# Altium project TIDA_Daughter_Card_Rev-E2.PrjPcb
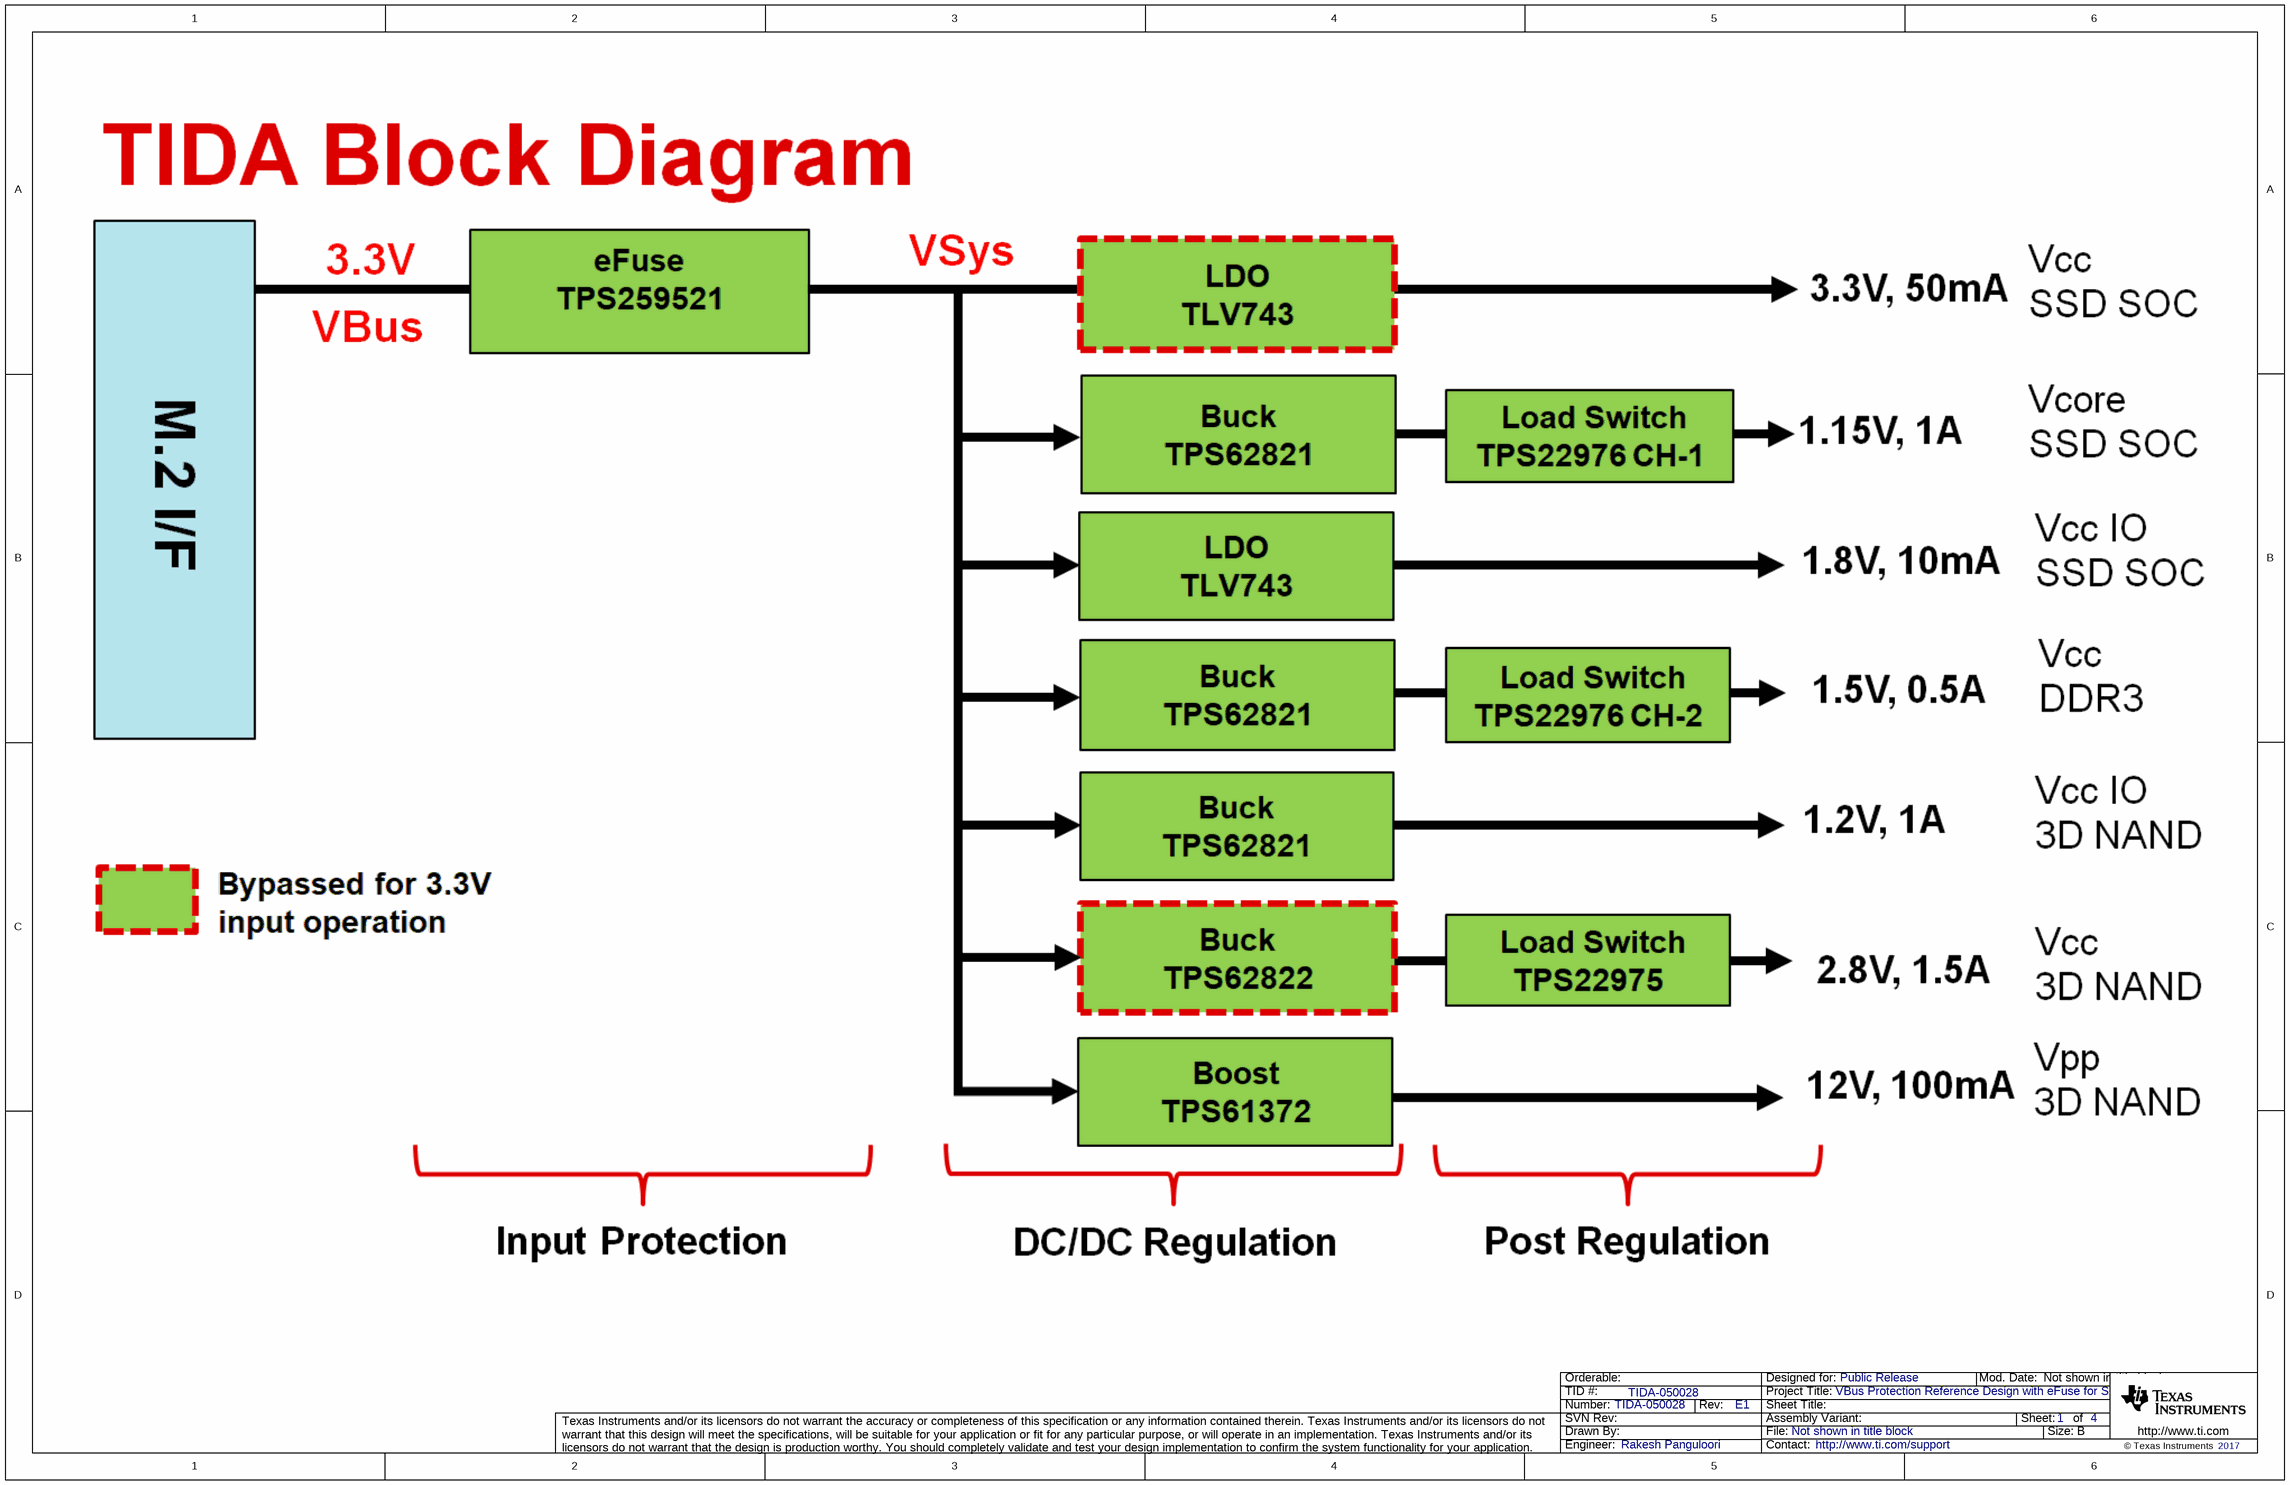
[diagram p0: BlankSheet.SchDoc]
CopyrightYear: 2017; PCB_Layout: Tessolve; PCB_Rev: E2; PRJ_Customer: Public Release; PRJ_Engineer: Rakesh Panguloori; PRJ_Number: TIDA-050028; PRJ_Title: VBus Protection Reference Design with eFuse for SSD Modules; SCH_Rev: E1; TechSupport: http://www.ti.com/support; TID: TIDA-050028
4 sheets, 81 parts. Net scope: flat (ports and power ports of the same name join across sheets).
Board file: TIDA_Daughter_Card_Rev-E2.PcbDoc
Sheets:
  BlankSheet.SchDoc
  Daughter_Card_Sheet1.SchDoc
  Daughter_Card_Sheet2.SchDoc
  EVM_Hardware.SchDoc

## Sheet BlankSheet.SchDoc
size 431 x 279 mm; Date: Not shown in title block; ApprovedBy: Not shown in title block; CheckedBy: Not shown in title block; Author: Not shown in title block; CompanyName: Not shown in title block; Engineer: Not shown in title block; Organization: Not shown in title block; Address1: Not shown in title block; Address2: Not shown in title block; Address3: Not shown in title block; Address4: Not shown in title block; DocumentNumber: 1; Revision: Use project parameter SCH_Rev; SheetNumber: 1; SheetTotal: 4; PageSetup: Record=PageOptions¦CenterHorizontal=True¦CenterVertical=True¦PrintScale=1.00¦XCorrection=1.00¦YCorrection=1.00¦PrintKind=0¦BorderSize=5000000¦LeftOffset=0¦BottomOffset=0¦Orientation=2¦PaperLength=1000¦PaperWidth=1000¦Scale=100¦PaperSource=15¦PrintQuality=600¦MediaType=1¦DitherType=10¦PaperKind=Letter¦PrintScaleMode=1; Orderable: N/A

## Sheet Daughter_Card_Sheet1.SchDoc
size 431 x 279 mm; Date: Not shown in title block; ApprovedBy: Not shown in title block; CheckedBy: Not shown in title block; Author: Not shown in title block; CompanyName: Not shown in title block; Engineer: Not shown in title block; Organization: Not shown in title block; Address1: Not shown in title block; Address2: Not shown in title block; Address3: Not shown in title block; Address4: Not shown in title block; DocumentNumber: 1; Revision: Use project parameter SCH_Rev; SheetNumber: 2; SheetTotal: 4; PageSetup: Record=PageOptions¦CenterHorizontal=True¦CenterVertical=True¦PrintScale=1.00¦XCorrection=1.00¦YCorrection=1.00¦PrintKind=0¦BorderSize=5000000¦LeftOffset=0¦BottomOffset=0¦Orientation=2¦PaperLength=1000¦PaperWidth=1000¦Scale=100¦PaperSource=15¦PrintQuality=600¦MediaType=1¦DitherType=10¦PaperKind=Letter¦PrintScaleMode=1; Orderable: N/A
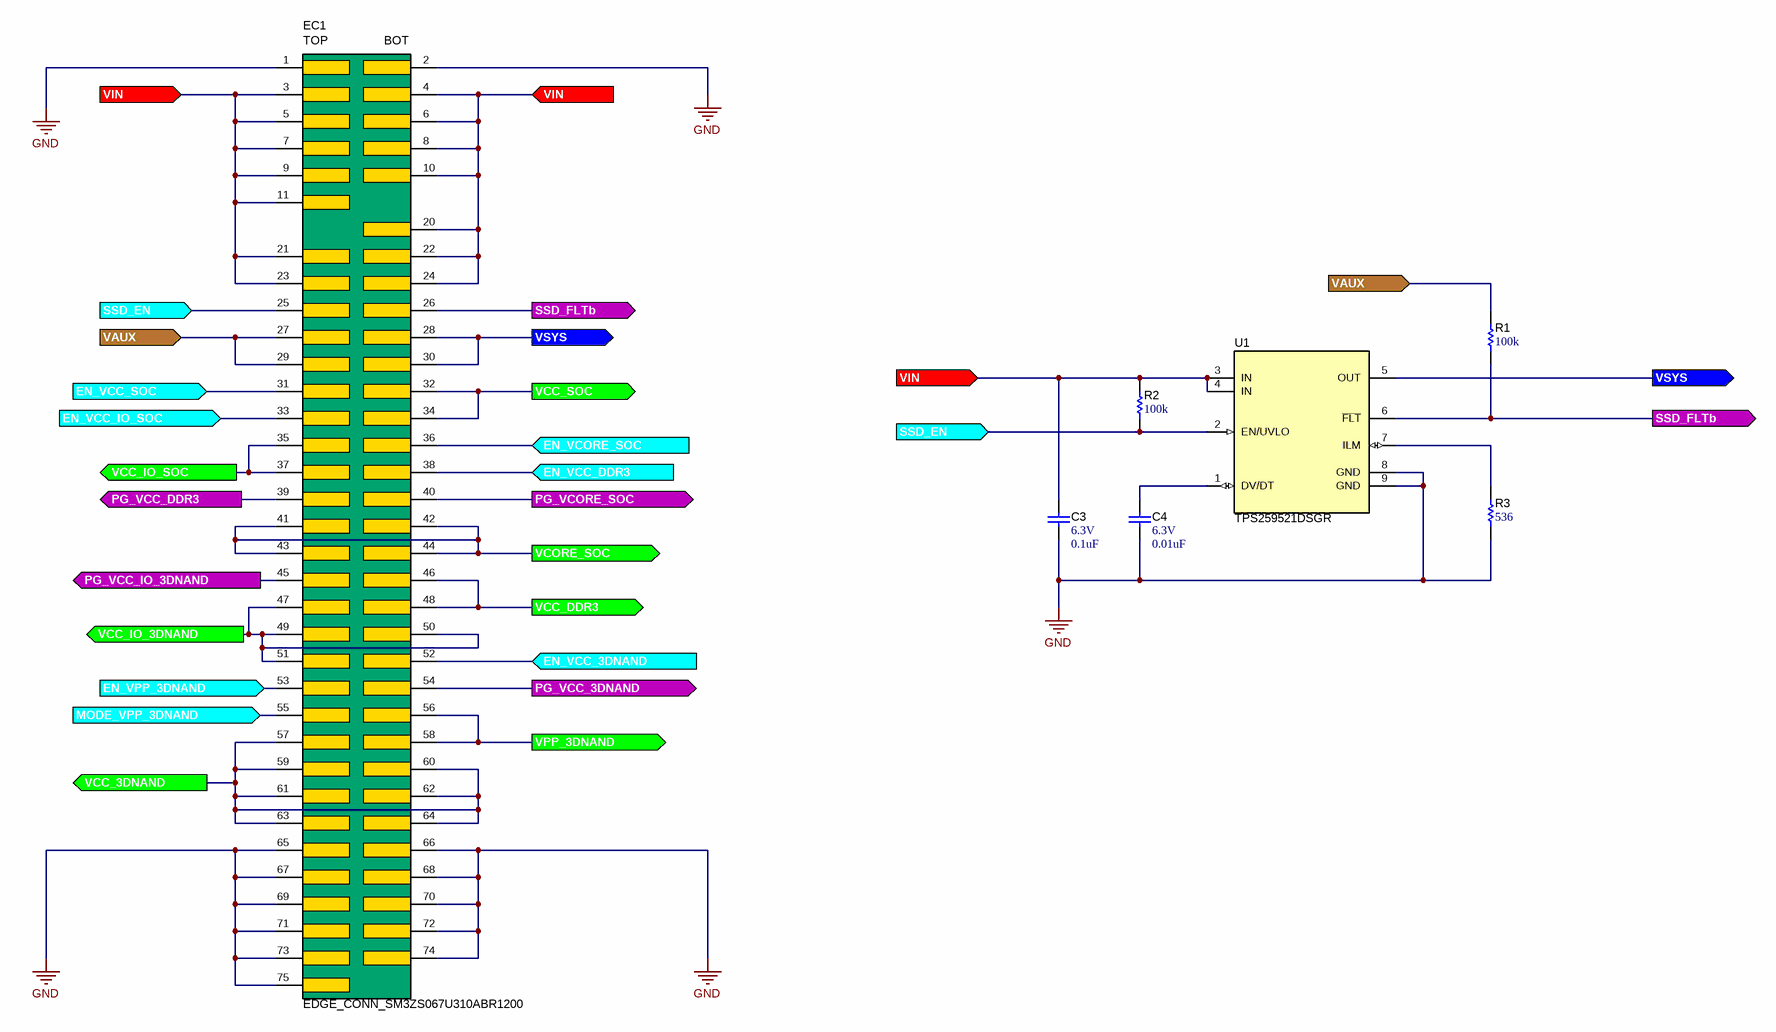
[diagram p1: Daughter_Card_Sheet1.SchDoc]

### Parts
C3  VDC_V: 6.3V  ValueDisplayed: 0.1uF  [0201_033]  (hidden comment: GRM033R60J104KE19D)
C4  VDC_V: 6.3V  ValueDisplayed: 0.01uF  [0201]  (hidden comment: GRM033R60J103KA01D)
EC1  EDGE_CONN_SM3ZS067U310ABR1200  [JAE_EDGE_CONN_SM3ZS067U310ABR1200]  (no BOM)
R1  ValueDisplayed: 100k  [0201]  (hidden comment: RC0201JR-07100KL)
R2  ValueDisplayed: 100k  [0201]  (hidden comment: RC0201JR-07100KL)
R3  ValueDisplayed: 536  [0201]  (hidden comment: RC0201FR-07536RL)
U1  TPS259521DSGR  [DSG0008A]

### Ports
EN_VCC_3DNAND (in), EN_VCC_DDR3 (in), EN_VCC_IO_SOC (in), EN_VCC_SOC (in), EN_VCORE_SOC (in), EN_VPP_3DNAND (in), MODE_VPP_3DNAND (in), PG_VCC_3DNAND (out), PG_VCC_DDR3 (out), PG_VCC_IO_3DNAND (out), PG_VCORE_SOC (out), SSD_EN (in), SSD_FLTb (out), VAUX (in), VCC_3DNAND (out), VCC_DDR3 (out), VCC_IO_3DNAND (out), VCC_IO_SOC (out), VCC_SOC (out), VCORE_SOC (out), VIN (in), VPP_3DNAND (out), VSYS (out)

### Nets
GND: C3.2 C4.2 EC1.1 EC1.2 EC1.65 EC1.66 EC1.67 EC1.68 EC1.69 EC1.70 EC1.71 EC1.72 EC1.73 EC1.74 EC1.75 R3.1 U1.8(GND) U1.9(GND)
EN_VCC_3DNAND: EC1.52 ; port EN_VCC_3DNAND
EN_VCC_DDR3: EC1.38 ; port EN_VCC_DDR3
EN_VCC_IO_SOC: EC1.33 ; port EN_VCC_IO_SOC
EN_VCC_SOC: EC1.31 ; port EN_VCC_SOC
EN_VCORE_SOC: EC1.36 ; port EN_VCORE_SOC
EN_VPP_3DNAND: EC1.53 ; port EN_VPP_3DNAND
MODE_VPP_3DNAND: EC1.55 ; port MODE_VPP_3DNAND
PG_VCC_3DNAND: EC1.54 ; port PG_VCC_3DNAND
PG_VCC_DDR3: EC1.39 ; port PG_VCC_DDR3
PG_VCC_IO_3DNAND: EC1.45 ; port PG_VCC_IO_3DNAND
PG_VCORE_SOC: EC1.40 ; port PG_VCORE_SOC
SSD_EN: EC1.25 R2.1 U1.2(EN/UVLO) ; port SSD_EN
SSD_FLTb: EC1.26 R1.1 U1.6(~{FLT}) ; port SSD_FLTb
VAUX: EC1.27 EC1.29 R1.2 ; port VAUX
VCC_3DNAND: EC1.57 EC1.59 EC1.60 EC1.61 EC1.62 EC1.63 EC1.64 ; port VCC_3DNAND
VCC_DDR3: EC1.46 EC1.48 ; port VCC_DDR3
VCC_IO_3DNAND: EC1.47 EC1.49 EC1.50 EC1.51 ; port VCC_IO_3DNAND
VCC_IO_SOC: EC1.35 EC1.37 ; port VCC_IO_SOC
VCC_SOC: EC1.32 EC1.34 ; port VCC_SOC
VCORE_SOC: EC1.41 EC1.42 EC1.43 EC1.44 ; port VCORE_SOC
VIN: C3.1 EC1.3 EC1.4 EC1.5 EC1.6 EC1.7 EC1.8 EC1.9 EC1.10 EC1.11 EC1.20 EC1.21 EC1.22 EC1.23 EC1.24 R2.2 U1.3(IN) U1.4(IN) ; port VIN
VPP_3DNAND: EC1.56 EC1.58 ; port VPP_3DNAND
VSYS: EC1.28 EC1.30 U1.5(OUT) ; port VSYS
NetC4_1: C4.1 U1.1(DV/DT)
NetR3_2: R3.2 U1.7(ILM)

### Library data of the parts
C3 = CMP-0009690-3: CAP, CERM, 0.1 uF, 6.3 V, +/- 10%, X5R, 0201; Manufacturer: MuRata; TaMin_C: -55°C; Polarized: N; SizeAreaWB_mm2: 2.08; Value1: Unknown; U/M: EA; Value: 0.1uF; TaMax_C: 85°C; SizeZ_mm: 0.33; SizeX_mm: 0.6; SizeY_mm: 0.3; Cap_Case: 0201; SizeArea_mm2: 0.18; Cap_F: 100nF; AEC Category: Q200
C4 = CMP-0009689-3: CAP, CERM, 0.01 uF, 6.3 V, +/- 10%, X5R, 0201; Manufacturer: MuRata; TaMin_C: -55°C; Polarized: N; SizeAreaWB_mm2: 2.08; Value1: Unknown; U/M: EA; Value: 0.01uF; TaMax_C: 85°C; SizeZ_mm: 0.26; SizeX_mm: 0.6; SizeY_mm: 0.3; SizeArea_mm2: 0.18; Cap_F: 10nF; AEC Category: Q200
EC1 = CMP-0075074-1: Connector, Card Edge 67-Pos, 0.5-mm Pitch, B Key; Manufacturer: JAE Electronics; CT: True; CompType: Card Edge Footprint; CNHeader: False
R1 R2 = CMP-0027017-1: RES, 100 k, 5%, 0.05 W, 0201; Manufacturer: Yageo America; Power_W: 50mW; TempCo: 200 ppm/C; U/M: EA; Value: 100k; EIA_Code: E24; SizeX_mm: 0.6; SizeY_mm: 0.3; SizeZ_mm: 0.26; Value2: 0.05W; SizeArea_mm2: 0.18; AEC Qualified: N; VDC_V: 25V; AEC Category: Q200
R3 = CMP-0027765-1: RES, 536, 1%, 0.05 W, 0201; Manufacturer: Yageo America; Power_W: 50mW; TempCo: 200 ppm/C; Value_Code: 536R; U/M: EA; Value: 536; EIA_Code: E96; SizeX_mm: 0.6; SizeY_mm: 0.3; SizeZ_mm: 0.26; Value2: 0.05W; SizeArea_mm2: 0.18; AEC Qualified: N; VDC_V: 25V; AEC Category: Q200
U1 = CMP-0013452-3: 12V eFuse with Over Voltage Protection, DSG0008A (WSON-8); Alternate PartNumber: TPS259521DSGT; Manufacturer: Texas Instruments; SizeZ_mm: 0.8; SizeX_mm: 2; SizeArea_mm2: 4; CompType: IC; U/M: EA; SizeAreaWB_mm2: 9

## Sheet Daughter_Card_Sheet2.SchDoc
size 431 x 279 mm; Date: Not shown in title block; ApprovedBy: Not shown in title block; CheckedBy: Not shown in title block; Author: Not shown in title block; CompanyName: Not shown in title block; Engineer: Not shown in title block; Organization: Not shown in title block; Address1: Not shown in title block; Address2: Not shown in title block; Address3: Not shown in title block; Address4: Not shown in title block; DocumentNumber: 1; Revision: Use project parameter SCH_Rev; SheetNumber: 3; SheetTotal: 4; PageSetup: Record=PageOptions¦CenterHorizontal=True¦CenterVertical=True¦PrintScale=1.00¦XCorrection=1.00¦YCorrection=1.00¦PrintKind=0¦BorderSize=5000000¦LeftOffset=0¦BottomOffset=0¦Orientation=2¦PaperLength=1000¦PaperWidth=1000¦Scale=100¦PaperSource=15¦PrintQuality=600¦MediaType=1¦DitherType=10¦PaperKind=Letter¦PrintScaleMode=1; Orderable: N/A
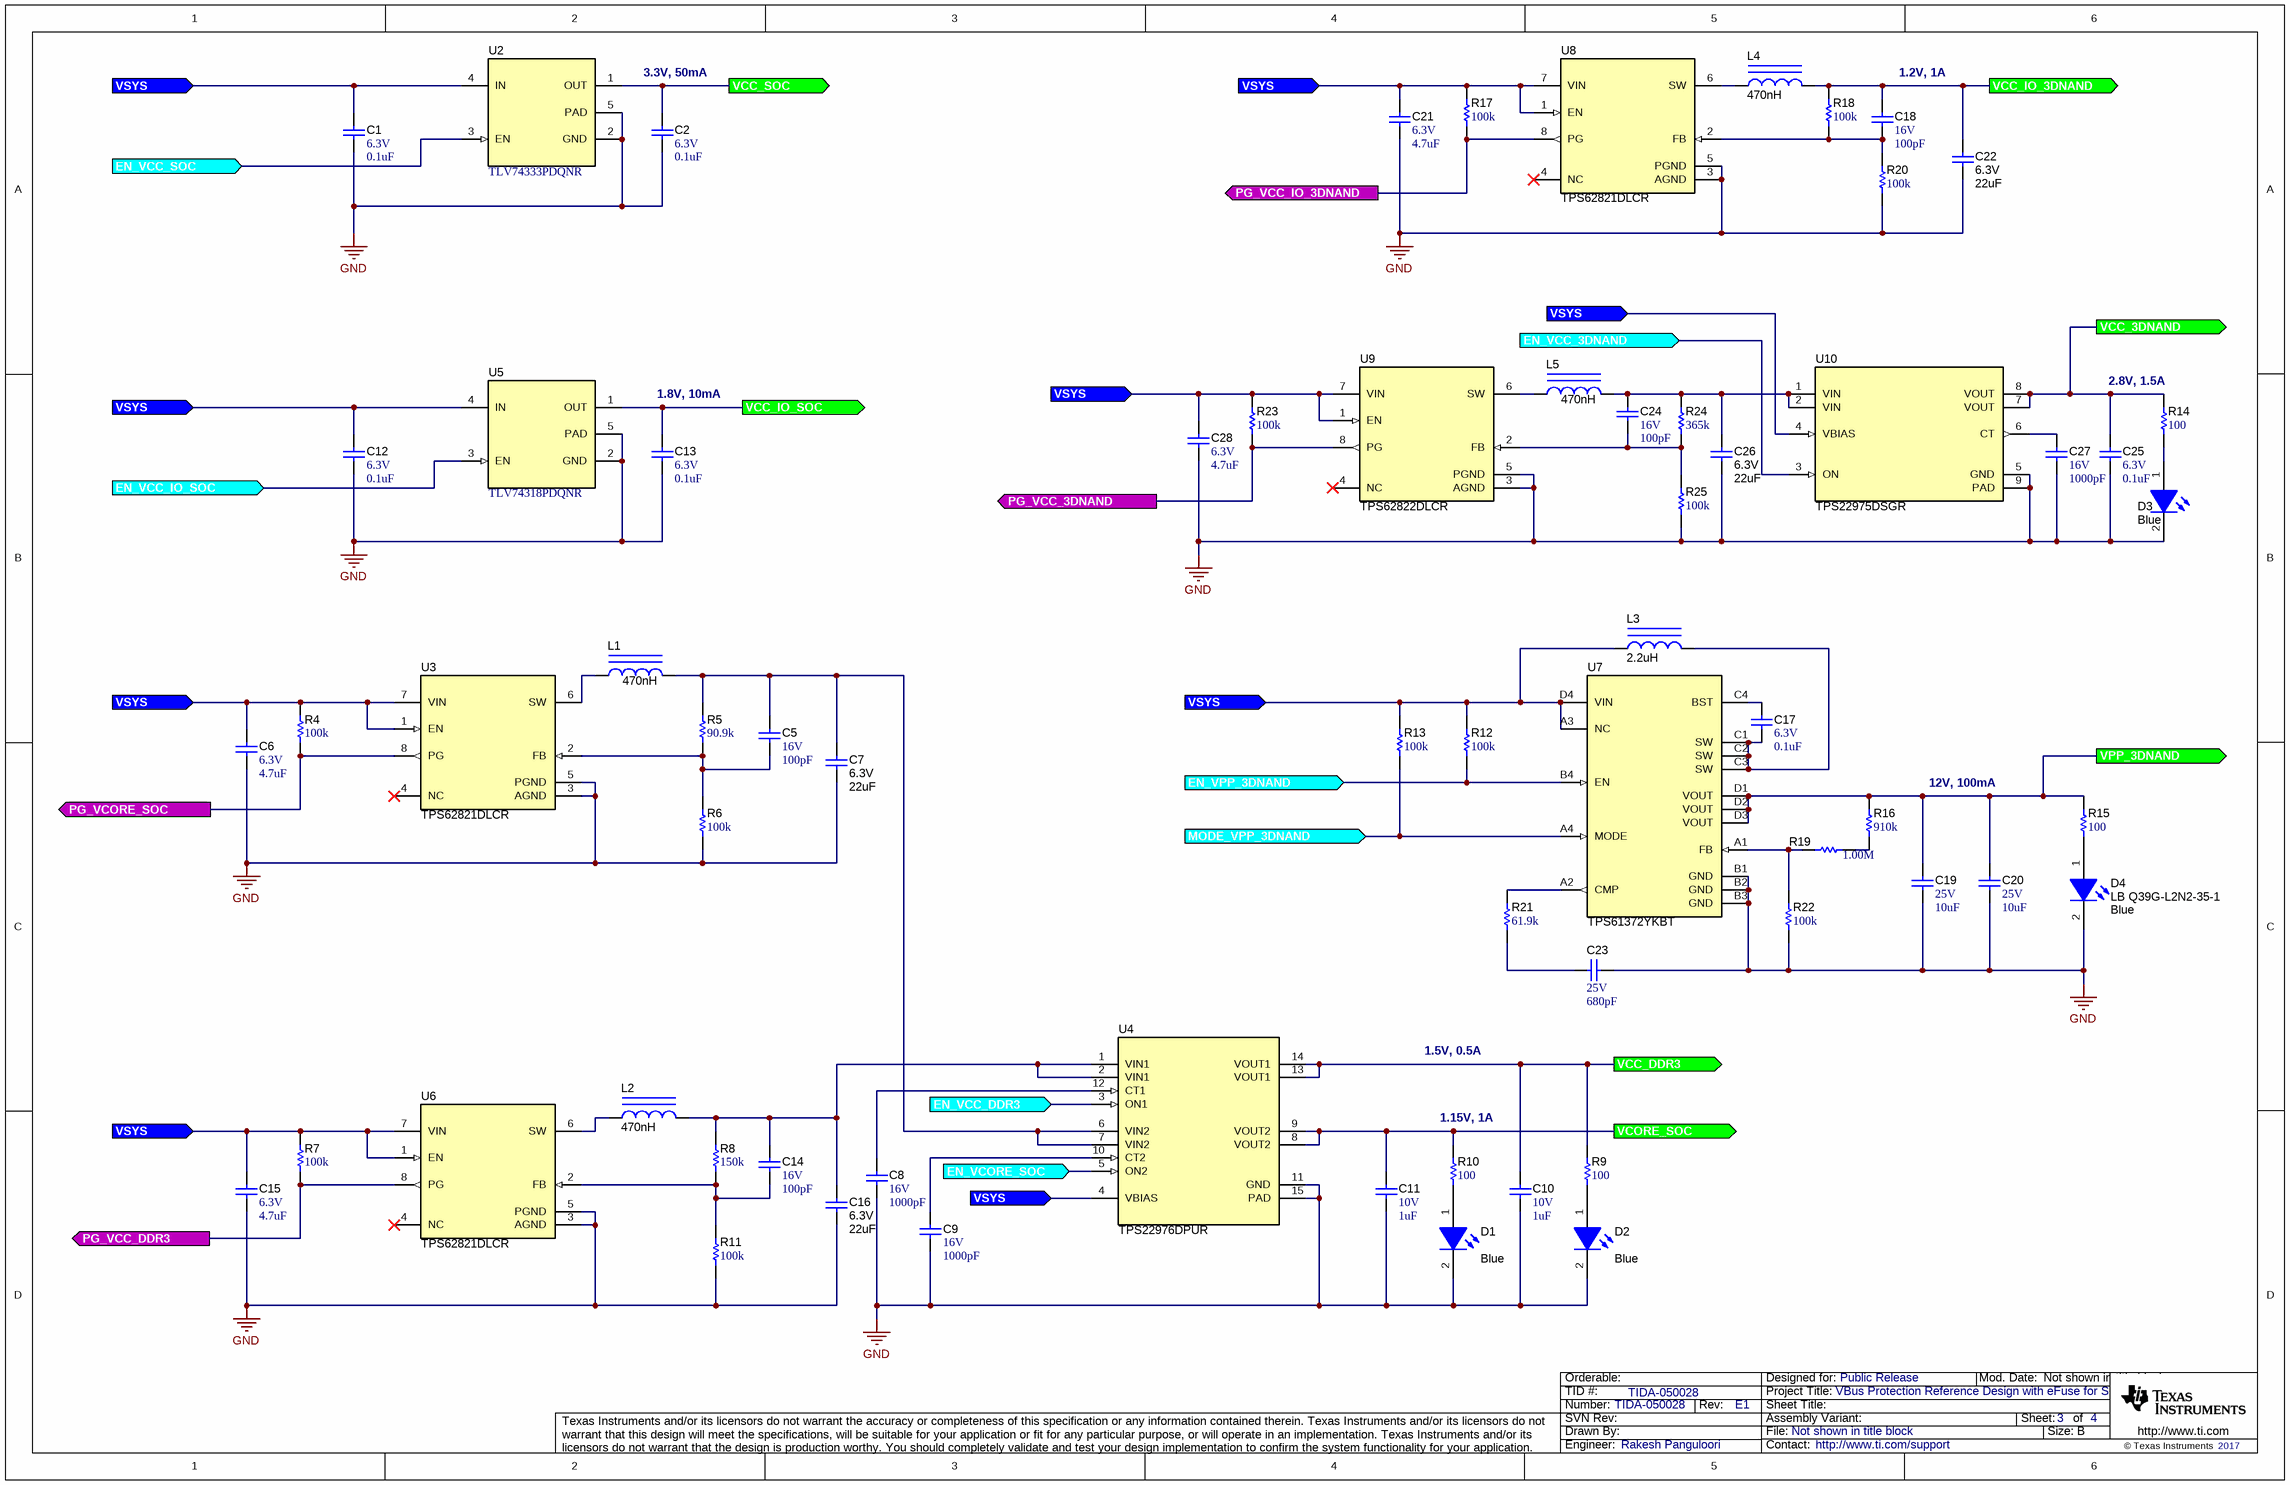
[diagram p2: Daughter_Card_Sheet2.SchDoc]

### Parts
C1  VDC_V: 6.3V  ValueDisplayed: 0.1uF  [0201_033]  (hidden comment: GRM033R60J104KE19D)
C2  VDC_V: 6.3V  ValueDisplayed: 0.1uF  [0201_033]  (hidden comment: GRM033R60J104KE19D)
C5  VDC_V: 16V  ValueDisplayed: 100pF  [0201]  (hidden comment: GRM033R71C101KA01D)
C6  VDC_V: 6.3V  ValueDisplayed: 4.7uF  [0201]  (hidden comment: GRM035R60J475ME15D)
C7  VDC_V: 6.3V  ValueDisplayed: 22uF  [0402S]  (hidden comment: GRM155R60J226ME11D)
C8  VDC_V: 16V  ValueDisplayed: 1000pF  [0201]  (hidden comment: GRM033R71C102KA01D)
C9  VDC_V: 16V  ValueDisplayed: 1000pF  [0201]  (hidden comment: GRM033R71C102KA01D)
C10  VDC_V: 10V  ValueDisplayed: 1uF  [0201]  (hidden comment: CL03A105MP3NSNC)
C11  VDC_V: 10V  ValueDisplayed: 1uF  [0201]  (hidden comment: CL03A105MP3NSNC)
C12  VDC_V: 6.3V  ValueDisplayed: 0.1uF  [0201_033]  (hidden comment: GRM033R60J104KE19D)
C13  VDC_V: 6.3V  ValueDisplayed: 0.1uF  [0201_033]  (hidden comment: GRM033R60J104KE19D)
C14  VDC_V: 16V  ValueDisplayed: 100pF  [0201]  (hidden comment: GRM033R71C101KA01D)
C15  VDC_V: 6.3V  ValueDisplayed: 4.7uF  [0201]  (hidden comment: GRM035R60J475ME15D)
C16  VDC_V: 6.3V  ValueDisplayed: 22uF  [0402S]  (hidden comment: GRM155R60J226ME11D)
C17  VDC_V: 6.3V  ValueDisplayed: 0.1uF  [0201_033]  (hidden comment: GRM033R60J104KE19D)
C18  VDC_V: 16V  ValueDisplayed: 100pF  [0201]  (hidden comment: GRM033R71C101KA01D)
C19  VDC_V: 25V  ValueDisplayed: 10uF  [0603]  (hidden comment: GRM188R61E106MA73D)
C20  VDC_V: 25V  ValueDisplayed: 10uF  [0603]  (hidden comment: GRM188R61E106MA73D)
C21  VDC_V: 6.3V  ValueDisplayed: 4.7uF  [0201]  (hidden comment: GRM035R60J475ME15D)
C22  VDC_V: 6.3V  ValueDisplayed: 22uF  [0402L]  (hidden comment: GRM155R60J226ME11D)
C23  VDC_V: 25V  ValueDisplayed: 680pF  [0201]  (hidden comment: GRM033R71E681KA01D)
C24  VDC_V: 16V  ValueDisplayed: 100pF  [0201]  (hidden comment: GRM033R71C101KA01D)
C25  VDC_V: 6.3V  ValueDisplayed: 0.1uF  [0201_033]  (hidden comment: GRM033R60J104KE19D)
C26  VDC_V: 6.3V  ValueDisplayed: 22uF  [0402L]  (hidden comment: GRM155R60J226ME11D)
C27  VDC_V: 16V  ValueDisplayed: 1000pF  [0201]  (hidden comment: GRM033R71C102KA01D)
C28  VDC_V: 6.3V  ValueDisplayed: 4.7uF  [0201]  (hidden comment: GRM035R60J475ME15D)
D1  value Blue  [LB Q39G_BLUE]  (hidden comment: LB Q39G-L2N2-35-1)
D2  value Blue  [LB Q39G_BLUE]  (hidden comment: LB Q39G-L2N2-35-1)
D3  value Blue  [LB Q39G_BLUE]  (hidden comment: LB Q39G-L2N2-35-1)
D4  LB Q39G-L2N2-35-1  value Blue  [LB Q39G_BLUE]
L1  ValueDisplayed: 470nH  [DFE201610E]  (hidden comment: DFE201610E-R47M=P2)
L2  ValueDisplayed: 470nH  [DFE201610E]  (hidden comment: DFE201610E-R47M=P2)
L3  ValueDisplayed: 2.2uH  [DFE322512]  (hidden comment: DFE322512F-2R2M=P2)
L4  ValueDisplayed: 470nH  [DFE201610E]  (hidden comment: DFE201610E-R47M=P2)
L5  ValueDisplayed: 470nH  [DFE201610E]  (hidden comment: DFE201610E-R47M=P2)
R4  ValueDisplayed: 100k  [0201]  (hidden comment: RC0201JR-07100KL)
R5  ValueDisplayed: 90.9k  [0201]  (hidden comment: RC0201FR-0790K9L)
R6  ValueDisplayed: 100k  [0201]  (hidden comment: RC0201JR-07100KL)
R7  ValueDisplayed: 100k  [0201]  (hidden comment: RC0201JR-07100KL)
R8  ValueDisplayed: 150k  [0201]  (hidden comment: RC0201FR-07150KL)
R9  ValueDisplayed: 100  [0201]  (hidden comment: RC0201JR-07100RL)
R10  ValueDisplayed: 100  [0201]  (hidden comment: RC0201JR-07100RL)
R11  ValueDisplayed: 100k  [0201]  (hidden comment: RC0201JR-07100KL)
R12  ValueDisplayed: 100k  [0201]  (hidden comment: RC0201JR-07100KL)
R13  ValueDisplayed: 100k  [0201]  (hidden comment: RC0201JR-07100KL)
R14  ValueDisplayed: 100  [0201]  (hidden comment: RC0201JR-07100RL)
R15  ValueDisplayed: 100  [0201]  (hidden comment: RC0201JR-07100RL)
R16  ValueDisplayed: 910k  [0201]  (hidden comment: RC0201JR-07910KL)
R17  ValueDisplayed: 100k  [0201]  (hidden comment: RC0201JR-07100KL)
R18  ValueDisplayed: 100k  [0201]  (hidden comment: RC0201JR-07100KL)
R19  ValueDisplayed: 1.00M  [0201]  (hidden comment: RC0201FR-071ML)
R20  ValueDisplayed: 100k  [0201]  (hidden comment: RC0201JR-07100KL)
R21  ValueDisplayed: 61.9k  [0201]  (hidden comment: RC0201FR-0761K9L)
R22  ValueDisplayed: 100k  [0201]  (hidden comment: RC0201JR-07100KL)
R23  ValueDisplayed: 100k  [0201]  (hidden comment: RC0201JR-07100KL)
R24  ValueDisplayed: 365k  [0201]  (hidden comment: RC0201FR-07365KL)
R25  ValueDisplayed: 100k  [0201]  (hidden comment: RC0201JR-07100KL)
U2  TLV74333PDQNR  [DQN0004A]
U3  TPS62821DLCR  [DLC0008A]
U4  TPS22976DPUR  [DPU0014A]
U5  TLV74318PDQNR  [DQN0004A]
U6  TPS62821DLCR  [DLC0008A]
U7  TPS61372YKBT  [YKB0016AEAG]
U8  TPS62821DLCR  [DLC0008A]
U9  TPS62822DLCR  [DLC0008A]
U10  TPS22975DSGR  [DSG0008A]

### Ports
EN_VCC_3DNAND (in), EN_VCC_DDR3 (in), EN_VCC_IO_SOC (in), EN_VCC_SOC (in), EN_VCORE_SOC (in), EN_VPP_3DNAND (in), MODE_VPP_3DNAND (in), PG_VCC_3DNAND (out), PG_VCC_DDR3 (out), PG_VCC_IO_3DNAND (out), PG_VCORE_SOC (out), VCC_3DNAND (out), VCC_DDR3 (out), VCC_IO_3DNAND (out), VCC_IO_SOC (out), VCC_SOC (out), VCORE_SOC (out), VPP_3DNAND (out), VSYS (in)

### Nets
GND: C1.2 C2.2 C6.2 C7.2 C8.2 C9.2 C10.2 C11.2 C12.2 C13.2 C15.2 C16.2 C19.2 C20.2 C21.2 C22.2 C23.1 C25.2 C26.2 C27.2 C28.2 D1.2(K) D2.2(K) D3.2(K) D4.2(K) R6.1 R11.1 R20.1 R22.1 R25.1 U2.2(GND) U2.5(PAD) U3.3(AGND) U3.5(PGND) U4.11(GND) U4.15(PAD) U5.2(GND) U5.5(PAD) U6.3(AGND) U6.5(PGND) U7.B1(GND) U7.B2(GND) U7.B3(GND) U8.3(AGND) U8.5(PGND) U9.3(AGND) U9.5(PGND) U10.5(GND) U10.9(PAD)
EN_VCC_3DNAND: U10.3(ON) ; port EN_VCC_3DNAND
EN_VCC_DDR3: U4.3(ON1) ; port EN_VCC_DDR3
EN_VCC_IO_SOC: U5.3(EN) ; port EN_VCC_IO_SOC
EN_VCC_SOC: U2.3(EN) ; port EN_VCC_SOC
EN_VCORE_SOC: U4.5(ON2) ; port EN_VCORE_SOC
EN_VPP_3DNAND: R12.1 U7.B4(EN) ; port EN_VPP_3DNAND
MODE_VPP_3DNAND: R13.2 U7.A4(MODE) ; port MODE_VPP_3DNAND
PG_VCC_3DNAND: R23.1 U9.8(PG) ; port PG_VCC_3DNAND
PG_VCC_DDR3: R7.1 U6.8(PG) ; port PG_VCC_DDR3
PG_VCC_IO_3DNAND: R17.1 U8.8(PG) ; port PG_VCC_IO_3DNAND
PG_VCORE_SOC: R4.1 U3.8(PG) ; port PG_VCORE_SOC
VCC_3DNAND: C25.1 R14.2 U10.7(VOUT) U10.8(VOUT) ; port VCC_3DNAND
VCC_DDR3: C10.1 R9.2 U4.13(VOUT1) U4.14(VOUT1) ; port VCC_DDR3
VCC_IO_3DNAND: C18.1 C22.1 L4.2 R18.2 ; port VCC_IO_3DNAND
VCC_IO_SOC: C13.1 U5.1(OUT) ; port VCC_IO_SOC
VCC_SOC: C2.1 U2.1(OUT) ; port VCC_SOC
VCORE_SOC: C11.1 R10.2 U4.8(VOUT2) U4.9(VOUT2) ; port VCORE_SOC
VPP_3DNAND: C19.1 C20.1 R15.2 R16.2 U7.D1(VOUT) U7.D2(VOUT) U7.D3(VOUT) ; port VPP_3DNAND
VSYS: C1.1 C6.1 C12.1 C15.1 C21.1 C28.1 L3.1 R4.2 R7.2 R12.2 R13.1 R17.2 R23.2 U2.4(IN) U3.1(EN) U3.7(VIN) U4.4(VBIAS) U5.4(IN) U6.1(EN) U6.7(VIN) U7.A3(NC) U7.D4(VIN) U8.1(EN) U8.7(VIN) U9.1(EN) U9.7(VIN) U10.4(VBIAS) ; port VSYS
NetC5_1: C5.1 C7.1 L1.2 R5.2 U4.6(VIN2) U4.7(VIN2)
NetC5_2: C5.2 R5.1 R6.2 U3.2(FB)
NetC8_1: C8.1 U4.12(CT1)
NetC9_1: C9.1 U4.10(CT2)
NetC14_1: C14.1 C16.1 L2.2 R8.2 U4.1(VIN1) U4.2(VIN1)
NetC14_2: C14.2 R8.1 R11.2 U6.2(FB)
NetC17_1: C17.1 U7.C4(BST)
NetC17_2: C17.2 L3.2 U7.C1(SW) U7.C2(SW) U7.C3(SW)
NetC18_2: C18.2 R18.1 R20.2 U8.2(FB)
NetC23_2: C23.2 R21.1
NetC24_1: C24.1 C26.1 L5.2 R24.2 U10.1(VIN) U10.2(VIN)
NetC24_2: C24.2 R24.1 R25.2 U9.2(FB)
NetC27_1: C27.1 U10.6(CT)
NetD1_1: D1.1(A) R10.1
NetD2_1: D2.1(A) R9.1
NetD3_1: D3.1(A) R14.1
NetD4_1: D4.1(A) R15.1
NetL1_1: L1.1 U3.6(SW)
NetL2_1: L2.1 U6.6(SW)
NetL4_1: L4.1 U8.6(SW)
NetL5_1: L5.1 U9.6(SW)
NetR16_1: R16.1 R19.2
NetR19_1: R19.1 R22.2 U7.A1(FB)
NetR21_2: R21.2 U7.A2(CMP)

Not connected (* = marked no-connect by the designer): U3 4(NC)*; U6 4(NC)*; U8 4(NC)*; U9 4(NC)*

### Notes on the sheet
- 3.3V, 50mA
- (near C18) 1.2V, 1A
- 1.8V, 10mA
- (near R14) 2.8V, 1.5A
- 12V, 100mA
- 1.5V, 0.5A
- (near R10) 1.15V, 1A

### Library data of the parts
C1 C2 C12 C13 C17 C25 = CMP-0009690-3: as C3 on sheet Daughter_Card_Sheet1
C5 C14 C18 C24 = CMP-0009744-1: CAP, CERM, 100 pF, 16 V, +/- 10%, X7R, 0201; Manufacturer: MuRata; TaMin_C: -55°C; Polarized: N; SizeAreaWB_mm2: 2.08; Value1: Unknown; U/M: EA; Value: 100pF; TaMax_C: 125°C; SizeZ_mm: 0.26; SizeX_mm: 0.6; SizeY_mm: 0.3; SizeArea_mm2: 0.18; AEC Category: Q200
C6 C15 C21 C28 = CMP-0009780-1: CAP, CERM, 4.7 uF, 6.3 V, +/- 20%, X5R, 0201; Manufacturer: MuRata; TaMin_C: -55°C; Polarized: N; SizeAreaWB_mm2: 2.08; Value1: Unknown; U/M: EA; Value: 4.7uF; TaMax_C: 85°C; SizeZ_mm: 0.26; SizeX_mm: 0.6; SizeY_mm: 0.3; SizeArea_mm2: 0.18; Cap_F: 4.7µF; AEC Category: Q200
C7 = CMP-0006545-2: CAP, CERM, 22 uF, 6.3 V, +/- 20%, X5R, 0402; Manufacturer: MuRata; TaMin_C: -55°C; Polarized: N; SizeAreaWB_mm2: 3; Value1: Unknown; U/M: EA; Value: 22uF; TaMax_C: 85°C; SizeZ_mm: 0.6; SizeY_mm: 0.5; Cap_Case: 0402; SizeX_mm: 1; Cap_F: 22µF; AEC Category: Q200
C8 C9 C27 = CMP-0009745-1: CAP, CERM, 1000 pF, 16 V, +/- 10%, X7R, 0201; Manufacturer: MuRata; TaMin_C: -55°C; Polarized: N; SizeAreaWB_mm2: 2.08; Value1: Unknown; U/M: EA; Value: 1000pF; TaMax_C: 125°C; SizeZ_mm: 0.26; SizeX_mm: 0.6; SizeY_mm: 0.3; SizeArea_mm2: 0.18; Cap_F: 1nF; AEC Category: Q200
C10 C11 = CMP-0009656-3: CAP, CERM, 1 uF, 10 V, +/- 20%, X5R, 0201; Manufacturer: Samsung Electro-Mechanics; TaMin_C: -55°C; Polarized: N; SizeAreaWB_mm2: 2.08; Value1: Unknown; U/M: EA; Value: 1uF; TaMax_C: 85°C; SizeZ_mm: 0.26; SizeX_mm: 0.6; SizeY_mm: 0.3; SizeArea_mm2: 0.18; Cap_F: 1µF; AEC Category: Q200
C16 C22 C26 = CMP-0006545-2: CAP, CERM, 22 uF, 6.3 V, +/- 20%, X5R, 0402; Manufacturer: MuRata; TaMin_C: -55°C; Polarized: N; SizeAreaWB_mm2: 3; Value1: Unknown; U/M: EA; Value: 22uF; TaMax_C: 85°C; SizeZ_mm: 0.6; SizeY_mm: 0.5; Cap_Case: 0402; CompType: Capacitor; SizeX_mm: 1; Cap_F: 22µF; AEC Category: Q200
C19 C20 = CMP-0007344-5: CAP, CERM, 10 uF, 25 V, +/- 20%, X5R, 0603; Manufacturer: MuRata; TaMin_C: -55°C; Polarized: N; SizeAreaWB_mm2: 4.68; Value1: Unknown; U/M: EA; Value: 10uF; TaMax_C: 85°C; SizeZ_mm: 1; SizeX_mm: 1.6; SizeY_mm: 0.8; SizeArea_mm2: 1.28; Cap_F: 10µF; AEC Category: Q200
C23 = CMP-0009776-1: CAP, CERM, 680 pF, 25 V, +/- 10%, X7R, 0201; Manufacturer: MuRata; TaMin_C: -55°C; Polarized: N; SizeAreaWB_mm2: 2.08; Value1: Unknown; U/M: EA; Value: 680pF; TaMax_C: 125°C; SizeZ_mm: 0.26; SizeX_mm: 0.6; SizeY_mm: 0.3; SizeArea_mm2: 0.18; AEC Category: Q200
D1-D4 = CMP-0002849-2: LED, Blue, SMD; Manufacturer: OSRAM; Tjmax_C: 95°C; Value1: W; Io_A: 1.5dA; Vf_V: 2.85V
L1 L2 L4 L5 = CMP-0077678-3: Inductor, Shielded, Metal Composite, 470 nH, 3.6 A, 0.032 ohm, SMD; Manufacturer: MuRata; Isat: 4.8A @ 30% inductance drop; Irms: 3.6A @ 40C rise; SizeAreaWB_mm2: 7.8; DCR_ohm: 0.032; Value: 470nH; Imax_A: 3.6A; SizeZ_mm: 1.0; SizeX_mm: 2.0; SizeY_mm: 1.6; SizeArea_mm2: 3.2; AEC Qualified: N; AEC Category: Q200
L3 = CMP-0058590-1: Inductor, Shielded, Metal Composite, 2.2 uH, 2.6 A, 0.066 ohm, SMD; Manufacturer: MuRata; Isat: 3.4A @ 30% inductance drop; Irms: 2.6A @ 40C rise; SizeAreaWB_mm2: 14.7; DCR_ohm: 0.066; Value: 2.2uH; Imax_A: 2.6A; SizeZ_mm: 1.2; SizeX_mm: 3.2; SizeY_mm: 2.5; SizeArea_mm2: 8; Ind_H: 2.2µH; AEC Qualified: N; AEC Category: Q200
R4 R6 R7 R11-R13 R17 R18 R20 R22 R23 R25 = CMP-0027017-1: as R1 on sheet Daughter_Card_Sheet1
R5 = CMP-0027918-1: RES, 90.9 k, 1%, 0.05 W, 0201; Manufacturer: Yageo America; Power_W: 50mW; TempCo: 200 ppm/C; Value_Code: 90k9; U/M: EA; Value: 90.9k; EIA_Code: E96; SizeX_mm: 0.6; SizeY_mm: 0.3; SizeZ_mm: 0.26; Value2: 0.05W; SizeArea_mm2: 0.18; AEC Qualified: N; VDC_V: 25V; AEC Category: Q200
R8 = CMP-0027366-2: RES, 150 k, 1%, 0.05 W, 0201; Manufacturer: Yageo America; Power_W: 50mW; TempCo: 200 ppm/C; U/M: EA; Value: 150k; EIA_Code: E96; SizeX_mm: 0.6; SizeY_mm: 0.3; SizeZ_mm: 0.26; Value2: 0.05W; SizeArea_mm2: 0.18; AEC Qualified: N; VDC_V: 25V; AEC Category: Q200
R9 R10 R14 R15 = CMP-0027018-3: RES, 100, 5%, 0.05 W, 0201; Manufacturer: Yageo America; Power_W: 50mW; TempCo: 200 ppm/C; Value_Code: 100R; U/M: EA; Value: 100; EIA_Code: E24; SizeX_mm: 0.6; SizeY_mm: 0.3; SizeZ_mm: 0.26; Value2: 0.05W; SizeArea_mm2: 0.18; AEC Qualified: N; VDC_V: 25V; AEC Category: Q200
R16 = CMP-0027177-1: RES, 910 k, 5%, 0.05 W, 0201; Manufacturer: Yageo America; Power_W: 50mW; TempCo: 200 ppm/C; U/M: EA; Value: 910k; EIA_Code: E24; SizeX_mm: 0.6; SizeY_mm: 0.3; SizeZ_mm: 0.26; Value2: 0.05W; SizeArea_mm2: 0.18; AEC Qualified: N; VDC_V: 25V; AEC Category: Q200
R19 = CMP-0027463-1: RES, 1.00 M, 1%, 0.05 W, 0201; Manufacturer: Yageo America; Power_W: 50mW; TempCo: 200 ppm/C; Value_Code: 1M00; U/M: EA; Value: 1.00Meg; EIA_Code: E96; Res_ohm: 1M; SizeX_mm: 0.6; SizeY_mm: 0.3; SizeZ_mm: 0.26; Value2: 0.05W; SizeArea_mm2: 0.18; AEC Qualified: N; VDC_V: 25V; AEC Category: Q200
R21 = CMP-0027811-1: RES, 61.9 k, 1%, 0.05 W, 0201; Manufacturer: Yageo America; Power_W: 50mW; TempCo: 200 ppm/C; Value_Code: 61k9; U/M: EA; Value: 61.9k; EIA_Code: E96; SizeX_mm: 0.6; SizeY_mm: 0.3; SizeZ_mm: 0.26; Value2: 0.05W; SizeArea_mm2: 0.18; AEC Qualified: N; VDC_V: 25V; AEC Category: Q200
R24 = CMP-0027630-1: RES, 365 k, 1%, 0.05 W, 0201; Manufacturer: Yageo America; Power_W: 50mW; TempCo: 200 ppm/C; U/M: EA; Value: 365k; EIA_Code: E96; SizeX_mm: 0.6; SizeY_mm: 0.3; SizeZ_mm: 0.26; Value2: 0.05W; SizeArea_mm2: 0.18; AEC Qualified: N; VDC_V: 25V; AEC Category: Q200
U2 = CMP-0065170-2: Low-Dropout Regulator, DQN0004A (X2SON-4); Manufacturer: Texas Instruments; SizeX_mm: 1.0; CompType: IC; SizeZ_mm: 0.4; SizeAreaWB_mm2: 4.0; U/M: EA
U3 U6 U8 = CMP-0065148-3: 1A Step-Down Converter With 1% Accuracy, DLC0008A (VSON-HR-8); Manufacturer: Texas Instruments; SizeX_mm: 1.5; SizeY_mm: 2.0; CompType: IC; SizeZ_mm: 1.0; SizeArea_mm2: 3.0; SizeAreaWB_mm2: 7.5; AEC Category: Q200; AEC Qualified: N
U4 = CMP-0073686-3: 5.5V, 6A, 14mΩ, Dual Load Switch with Adj. Rise Time & Optional QOD, DPU0014A (WSON-14); Alternate PartNumber: TPS22976DPUT; Alternate Manufacturer: Texas Instruments; Green_Lifecycle: Active; SizeAreaWB_mm2: 12.0; Green_REACh: Passed; SizeZ_mm: 0.8; SizeX_mm: 2.0; SizeY_mm: 3.0; SizeArea_mm2: 6.0; CompType: IC; AEC Category: Q200; AEC Qualified: N
U5 = CMP-0065161-2: Low-Dropout Regulator, DQN0004A (X2SON-4); Manufacturer: Texas Instruments; SizeX_mm: 1.0; CompType: IC; SizeZ_mm: 0.4; SizeAreaWB_mm2: 4.0; U/M: EA
U7 = CMP-0081181-1: 16-V, 3.6-A Synchronous Boost with Short Protection and Load Disconnect, YKB0016AEAG (DSBGA-16); Alternate PartNumber: TPS61372YKBR; Alternate Manufacturer: Texas Instruments; SizeAreaWB_mm2: 6.1746; SizeZ_mm: 0.5; SizeX_mm: 1.46; SizeY_mm: 1.51; SizeArea_mm2: 2.2046; CompType: IC; AEC Qualified: N; AEC Category: Q200
U9 = CMP-0077166-2: 2A Step-Down Converter With 1% Accuracy, DLC0008A (VSON-HR-8); Alternate PartNumber: TPS62822DLCT; Alternate Manufacturer: Texas Instruments; SizeX_mm: 1.5; CompType: IC; SizeAreaWB_mm2: 7.5; SizeZ_mm: 1.0; SizeY_mm: 2.0; SizeArea_mm2: 3.0; AEC Category: Q200; AEC Qualified: N
U10 = CMP-0073684-2: 5.7V, 6A, 16mΩ Load Switch with Adjustable Rise Time & Optional QOD for Cost-Conscious Applications, DSG0008A (WSON-8); Alternate PartNumber: TPS22975DSGT; Manufacturer: Texas Instruments; SizeZ_mm: 0.8; SizeX_mm: 2.0; SizeArea_mm2: 4.0; CompType: IC; U/M: EA; SizeAreaWB_mm2: 9.0

## Sheet EVM_Hardware.SchDoc
size 431 x 279 mm; Date: Not shown in title block; ApprovedBy: Not shown in title block; CheckedBy: Not shown in title block; Author: Not shown in title block; CompanyName: Not shown in title block; Engineer: Not shown in title block; Organization: Not shown in title block; Address1: Not shown in title block; Address2: Not shown in title block; Address3: Not shown in title block; Address4: Not shown in title block; DocumentNumber: 1; Revision: Use project parameter SCH_Rev; SheetNumber: 4; SheetTotal: 4; PageSetup: Record=PageOptions¦CenterHorizontal=True¦CenterVertical=True¦PrintScale=1.00¦XCorrection=1.00¦YCorrection=1.00¦PrintKind=0¦BorderSize=5000000¦LeftOffset=0¦BottomOffset=0¦Orientation=2¦PaperLength=1000¦PaperWidth=1000¦Scale=100¦PaperSource=15¦PrintQuality=600¦MediaType=1¦DitherType=10¦PaperKind=Letter¦PrintScaleMode=1
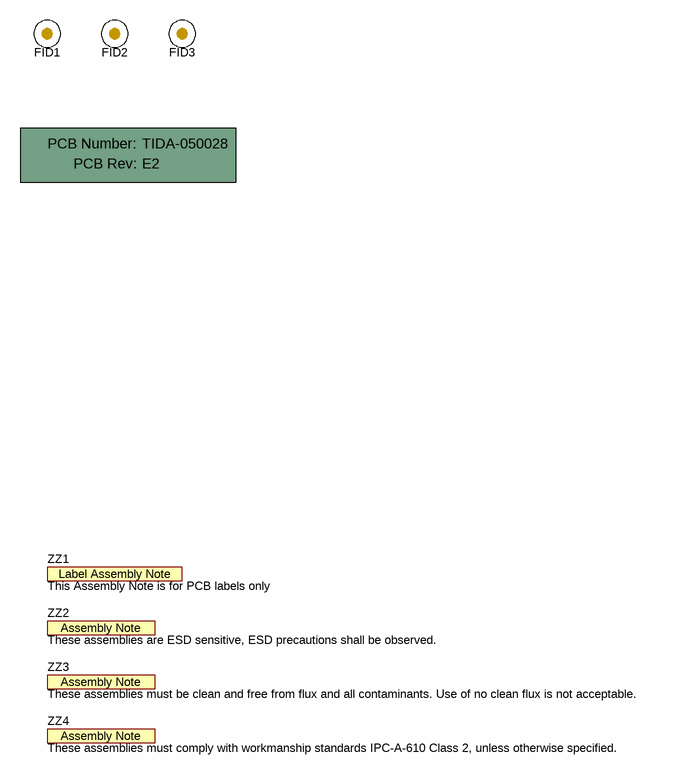
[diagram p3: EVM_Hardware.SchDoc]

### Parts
!PCB1  Printed Circuit Board  (value not drawn)  (mechanical)
FID1  Fiducial  [Fiducial10-20]  (value not drawn)
FID2  Fiducial  [Fiducial10-20]  (value not drawn)
FID3  Fiducial  [Fiducial10-20]  (value not drawn)
ZZ1  This Assembly Note is for PCB labels only  [AssemblyNoteLabel]  (no BOM)
ZZ2  These assemblies are ESD sensitive, ESD precautions shall be observed.  [AssemblyNote]  (no BOM)
ZZ3  These assemblies must be clean and free from flux and all contaminants. Use of no clean flux is not acceptable.  [AssemblyNote]  (no BOM)
ZZ4  These assemblies must comply with workmanship standards IPC-A-610 Class 2, unless otherwise specified.  [AssemblyNote]  (no BOM)

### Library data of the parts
!PCB1 = CMP-0003618-2: Manufacturer: Any; PartNumber: TIDA-050028
FID1-FID3 = CMP-0077181-1: Fiducial mark.  There is nothing to buy or mount.
ZZ1 = CMP-0003616-3
ZZ2 = CMP-0077236-1
ZZ3 = CMP-0077237-1
ZZ4 = CMP-0077238-1

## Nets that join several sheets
GND: Daughter_Card_Sheet1 (18 pins), Daughter_Card_Sheet2 (49 pins)
EN_VCC_3DNAND: Daughter_Card_Sheet1 (EC1.52), Daughter_Card_Sheet2 (U10.3)
EN_VCC_DDR3: Daughter_Card_Sheet1 (EC1.38), Daughter_Card_Sheet2 (U4.3)
EN_VCC_IO_SOC: Daughter_Card_Sheet1 (EC1.33), Daughter_Card_Sheet2 (U5.3)
EN_VCC_SOC: Daughter_Card_Sheet1 (EC1.31), Daughter_Card_Sheet2 (U2.3)
EN_VCORE_SOC: Daughter_Card_Sheet1 (EC1.36), Daughter_Card_Sheet2 (U4.5)
EN_VPP_3DNAND: Daughter_Card_Sheet1 (EC1.53), Daughter_Card_Sheet2 (R12.1 U7.B4)
MODE_VPP_3DNAND: Daughter_Card_Sheet1 (EC1.55), Daughter_Card_Sheet2 (R13.2 U7.A4)
PG_VCC_3DNAND: Daughter_Card_Sheet1 (EC1.54), Daughter_Card_Sheet2 (R23.1 U9.8)
PG_VCC_DDR3: Daughter_Card_Sheet1 (EC1.39), Daughter_Card_Sheet2 (R7.1 U6.8)
PG_VCC_IO_3DNAND: Daughter_Card_Sheet1 (EC1.45), Daughter_Card_Sheet2 (R17.1 U8.8)
PG_VCORE_SOC: Daughter_Card_Sheet1 (EC1.40), Daughter_Card_Sheet2 (R4.1 U3.8)
VCC_3DNAND: Daughter_Card_Sheet1 (7 pins), Daughter_Card_Sheet2 (C25.1 R14.2 U10.7 U10.8)
VCC_DDR3: Daughter_Card_Sheet1 (EC1.46 EC1.48), Daughter_Card_Sheet2 (C10.1 R9.2 U4.13 U4.14)
VCC_IO_3DNAND: Daughter_Card_Sheet1 (EC1.47 EC1.49 EC1.50 EC1.51), Daughter_Card_Sheet2 (C18.1 C22.1 L4.2 R18.2)
VCC_IO_SOC: Daughter_Card_Sheet1 (EC1.35 EC1.37), Daughter_Card_Sheet2 (C13.1 U5.1)
VCC_SOC: Daughter_Card_Sheet1 (EC1.32 EC1.34), Daughter_Card_Sheet2 (C2.1 U2.1)
VCORE_SOC: Daughter_Card_Sheet1 (EC1.41 EC1.42 EC1.43 EC1.44), Daughter_Card_Sheet2 (C11.1 R10.2 U4.8 U4.9)
VPP_3DNAND: Daughter_Card_Sheet1 (EC1.56 EC1.58), Daughter_Card_Sheet2 (7 pins)
VSYS: Daughter_Card_Sheet1 (EC1.28 EC1.30 U1.5), Daughter_Card_Sheet2 (27 pins)

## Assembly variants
001: not fitted FID1 FID2 FID3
